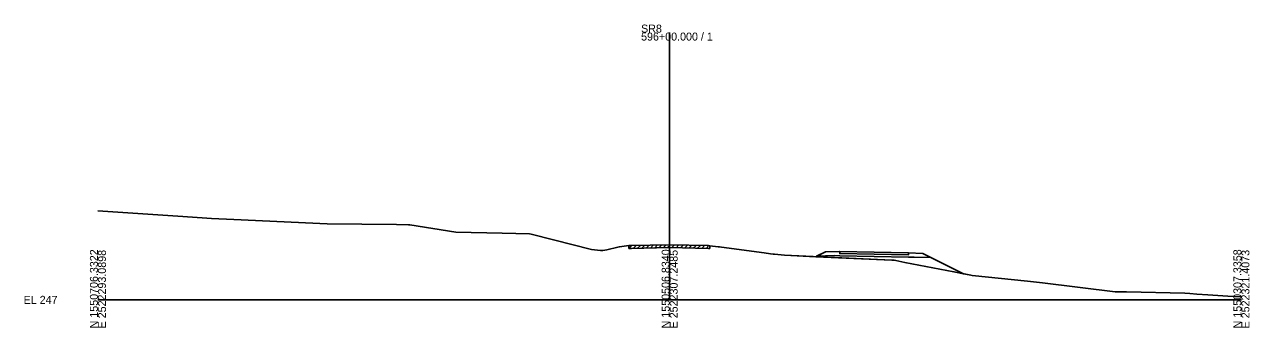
# Model space of a CAD drawing. Extents: x -26 to 2803, y -10 to 19537.
# Drawn here: x -25.7 to 402.8, y 5490.3 to 5596.4 of the extents above; entities that cross this region are included whole.
import ezdxf

# ---------------------------------------------------------------- set-up
doc = ezdxf.new("R2010")
doc.units = 0
for name, color, linetype in [('50', 7, 'Continuous'), ('XS_CELL', 7, 'Continuous'), ('XS_M_MULTI', 7, 'Continuous'), ('XS_M_SHAPES_EARTHWORK', 7, 'Continuous'), ('XS_P_FINISHED_GRADE', 7, 'Continuous'), ('XS_P_SUBGRADE_GRANULAR', 7, 'Continuous'), ('XS_P_SUBGRADE_PAVEMENT', 7, 'Continuous'), ('XS_X_GROUND', 7, 'Continuous')]:
    doc.layers.add(name, color=color, linetype=linetype)

msp = doc.modelspace()

# ---------------------------------------------------------------- linework, layer by layer
at = {"layer": '50'}
for p, q in [((185.76, 5517.98), (186.78, 5519)), ((185.76, 5517.98), (185.76, 5518.98)), ((185.76, 5517.98), (186.68, 5518)), ((186.68, 5518), (199.68, 5518.31)), ((187.26, 5518.01), (188.28, 5519.04)), ((188.76, 5518.05), (189.78, 5519.07)), ((190.26, 5518.08), (191.28, 5519.11)), ((191.76, 5518.12), (192.78, 5519.14)), ((193.26, 5518.15), (194.28, 5519.18)), ((194.76, 5518.19), (195.78, 5519.21)), ((196.26, 5518.22), (197.28, 5519.25)), ((197.76, 5518.26), (198.78, 5519.28)), ((199.26, 5518.3), (200.25, 5519.29)), ((199.68, 5518.31), (200, 5518.3)), ((200, 5518.3), (213.57, 5517.97)), ((200.76, 5518.28), (201.74, 5519.26)), ((202.26, 5518.24), (203.24, 5519.22)), ((203.76, 5518.21), (204.74, 5519.18)), ((205.26, 5518.17), (206.24, 5519.15)), ((206.76, 5518.14), (207.74, 5519.11)), ((208.26, 5518.1), (209.24, 5519.08)), ((209.76, 5518.06), (210.74, 5519.04)), ((211.26, 5518.03), (212.24, 5519)), ((212.76, 5517.99), (213.74, 5518.97)), ((213.57, 5517.97), (214.03, 5517.96)), ((214.03, 5518.96), (214.03, 5517.96))]:
    msp.add_line(p, q, dxfattribs=at)
at = {"layer": 'XS_CELL'}
for p, q in [((200, 5500), (200, 5593.58)), ((0, 5500), (200, 5500)), ((200, 5500), (400, 5500))]:
    msp.add_line(p, q, dxfattribs=at)
at = {"layer": 'XS_M_MULTI'}
for p, q in [((251.1, 5515.1), (254.46, 5516.78)), ((254.46, 5516.78), (259.48, 5516.98)), ((259.48, 5516.98), (271.51, 5516.72)), ((271.51, 5516.72), (283.53, 5516.45)), ((283.53, 5516.45), (288.55, 5516.25)), ((288.55, 5516.25), (302.81, 5509.14))]:
    msp.add_line(p, q, dxfattribs=at)
for points in [[(0, 5531.19), (27.92, 5529.28), (36.49, 5528.69), (39.74, 5528.47), (47.53, 5528.11), (80.22, 5526.6), (104.42, 5526.34), (108.65, 5526.3), (109.11, 5526.23), (125.2, 5523.72), (141.43, 5523.39), (151.01, 5523.09), (151.54, 5522.96), (159.38, 5521), (172.63, 5517.67), (174.71, 5517.38), (175.85, 5517.22), (176.57, 5517.31), (178, 5517.49), (181.88, 5518.47), (182.42, 5518.61), (185.76, 5518.98), (186.68, 5519), (199.68, 5519.31), (200, 5519.3), (213.57, 5518.97), (214.03, 5518.96), (216.97, 5518.59), (217.39, 5518.54), (218.09, 5518.44), (233.05, 5516.44), (235.31, 5516.14), (236.22, 5516.02), (236.71, 5515.95), (240.12, 5515.6), (251.1, 5515.1)], [(302.81, 5509.14), (305.4, 5508.62), (305.85, 5508.57), (325.22, 5506.59), (330.4, 5505.99), (355.84, 5502.84), (357.67, 5502.85), (359.81, 5502.8), (380.22, 5502.29), (381.92, 5502.18), (384.38, 5502.01), (388.25, 5501.76), (395.22, 5501.29), (400, 5501.05)]]:
    msp.add_lwpolyline(points, dxfattribs=at)
at = {"layer": 'XS_M_SHAPES_EARTHWORK'}
for points in [[(257.51, 5515.5), (251.4, 5515.25), (251.1, 5515.1), (277.73, 5513.89), (278.48, 5513.87), (279.11, 5513.79), (282.28, 5513.12), (299.42, 5509.81), (302.81, 5509.14), (291.42, 5514.82), (285.51, 5514.94), (283.51, 5514.98), (271.51, 5515.22), (259.51, 5515.46)], [(259.48, 5516.98), (259.51, 5516.98), (259.51, 5516.21), (271.51, 5515.97), (283.51, 5515.73), (283.51, 5516.46), (283.53, 5516.45), (288.55, 5516.25), (291.42, 5514.82), (285.51, 5514.94), (283.51, 5514.98), (271.51, 5515.22), (259.51, 5515.46), (257.51, 5515.5), (251.4, 5515.25), (254.46, 5516.78)], [(283.51, 5515.73), (283.51, 5516.46), (271.51, 5516.72), (259.51, 5516.98), (259.51, 5516.21), (271.51, 5515.97)]]:
    msp.add_lwpolyline(points, close=True, dxfattribs=at)
at = {"layer": 'XS_P_FINISHED_GRADE'}
for p, q in [((254.46, 5516.78), (251.1, 5515.1)), ((259.48, 5516.98), (254.46, 5516.78)), ((259.48, 5516.98), (271.51, 5516.72)), ((271.51, 5516.72), (283.53, 5516.45)), ((283.53, 5516.45), (288.55, 5516.25)), ((288.55, 5516.25), (302.81, 5509.14))]:
    msp.add_line(p, q, dxfattribs=at)
at = {"layer": 'XS_P_SUBGRADE_GRANULAR'}
for p, q in [((257.51, 5515.5), (251.4, 5515.25)), ((259.51, 5515.46), (257.51, 5515.5)), ((259.51, 5515.46), (271.51, 5515.22)), ((271.51, 5515.22), (283.51, 5514.98)), ((283.51, 5514.98), (285.51, 5514.94)), ((285.51, 5514.94), (291.42, 5514.82))]:
    msp.add_line(p, q, dxfattribs=at)
at = {"layer": 'XS_P_SUBGRADE_PAVEMENT'}
for p, q in [((259.51, 5516.21), (259.51, 5516.98)), ((259.51, 5516.21), (271.51, 5515.97)), ((271.51, 5515.97), (283.51, 5515.73)), ((283.51, 5515.73), (283.51, 5516.46))]:
    msp.add_line(p, q, dxfattribs=at)
at = {"layer": 'XS_X_GROUND'}
msp.add_lwpolyline([(0, 5531.19), (27.92, 5529.28), (36.49, 5528.69), (39.74, 5528.47), (47.53, 5528.11), (80.22, 5526.6), (104.42, 5526.34), (108.65, 5526.3), (109.11, 5526.23), (125.2, 5523.72), (141.43, 5523.39), (151.01, 5523.09), (151.54, 5522.96), (159.38, 5521), (172.63, 5517.67), (174.71, 5517.38), (175.85, 5517.22), (176.57, 5517.31), (178, 5517.49), (181.88, 5518.47), (182.42, 5518.61), (185.76, 5518.98), (186.68, 5519), (199.68, 5519.31), (200, 5519.3), (213.57, 5518.97), (214.03, 5518.96), (216.97, 5518.59), (217.39, 5518.54), (218.09, 5518.44), (233.05, 5516.44), (235.31, 5516.14), (236.22, 5516.02), (236.71, 5515.95), (240.12, 5515.6), (277.73, 5513.89), (278.48, 5513.87), (279.11, 5513.79), (282.28, 5513.12), (299.42, 5509.81), (305.4, 5508.62), (305.85, 5508.57), (325.22, 5506.59), (330.4, 5505.99), (355.84, 5502.84), (357.67, 5502.85), (359.81, 5502.8), (380.22, 5502.29), (381.92, 5502.18), (384.38, 5502.01), (388.25, 5501.76), (395.22, 5501.29), (400, 5501.05)], dxfattribs=at)

# ---------------------------------------------------------------- texts
at = {"layer": 'XS_CELL'}
for s, p in [('596+00.000 / 1', (190, 5590.78)), ('SR8', (190, 5593.58)), ('EL 247', (-26, 5498.6))]:
    msp.add_text(s, height=2.8, dxfattribs=at).set_placement(p)
for s, p in [('N 1550706.3322', (0, 5490)), ('E 2522293.0898', (2.8, 5490)), ('N 1550506.8340', (200, 5490)), ('E 2522307.2485', (202.8, 5490)), ('N 1550307.3358', (400, 5490)), ('E 2522321.4073', (402.8, 5490))]:
    msp.add_text(s, height=2.8, rotation=90, dxfattribs=at).set_placement(p)

doc.saveas('drawing.dxf')
